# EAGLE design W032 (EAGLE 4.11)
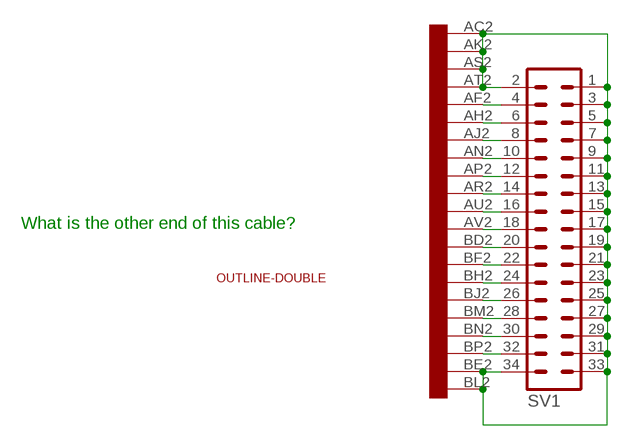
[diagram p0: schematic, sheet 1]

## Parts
SV1  MA17-2  [MA17-2]
U$1  OUTLINE-DOUBLE  [DOUBLE]
U$2  DOUBLE  [EDGE-CON4]

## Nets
GND: SV1.1 SV1.2 SV1.3 SV1.5 SV1.7 SV1.9 SV1.11 SV1.13 SV1.15 SV1.17 SV1.19 SV1.21 SV1.23 SV1.25 SV1.27 SV1.29 SV1.31 SV1.33 SV1.34 U$2.AC2 U$2.AK2 U$2.AS2 U$2.AT2 U$2.BE2 U$2.BL2
N$2: SV1.4 U$2.AF2
N$3: SV1.6 U$2.AH2
N$4: SV1.8 U$2.AJ2
N$5: SV1.10 U$2.AN2
N$6: SV1.12 U$2.AP2
N$7: SV1.14 U$2.AR2
N$8: SV1.16 U$2.AU2
N$9: SV1.18 U$2.AV2
N$10: SV1.20 U$2.BD2
N$11: SV1.22 U$2.BF2
N$12: SV1.24 U$2.BH2
N$13: SV1.26 U$2.BJ2
N$14: SV1.28 U$2.BM2
N$15: SV1.30 U$2.BN2
N$16: SV1.32 U$2.BP2
Unconnected: U$2.AA1 U$2.AA2 U$2.AB1 U$2.AB2 U$2.AC1 U$2.AD1 U$2.AD2 U$2.AE1 U$2.AE2 U$2.AF1 U$2.AH1 U$2.AJ1 U$2.AK1 U$2.AL1 U$2.AL2 U$2.AM1 U$2.AM2 U$2.AN1 U$2.AP1 U$2.AR1 U$2.AS1 U$2.AT1 U$2.AU1 U$2.AV1 U$2.BA1 U$2.BA2 U$2.BB1 U$2.BB2 U$2.BC1 U$2.BC2 U$2.BD1 U$2.BE1 U$2.BF1 U$2.BH1 U$2.BJ1 U$2.BK1 U$2.BK2 U$2.BL1 U$2.BM1 U$2.BN1 U$2.BP1 U$2.BR1 U$2.BR2 U$2.BS1 U$2.BS2 U$2.BT1 U$2.BT2 U$2.BU1 U$2.BU2 U$2.BV1 U$2.BV2

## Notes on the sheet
- What is the other end of this cable?

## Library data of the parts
SV1 = con-lstb:MA17-2: PIN HEADER
U$1 = dec-con:OUTLINE-*: Board outlines for DEC boards.
U$2 = dec-con:DOUBLE: Double-Height DEC board

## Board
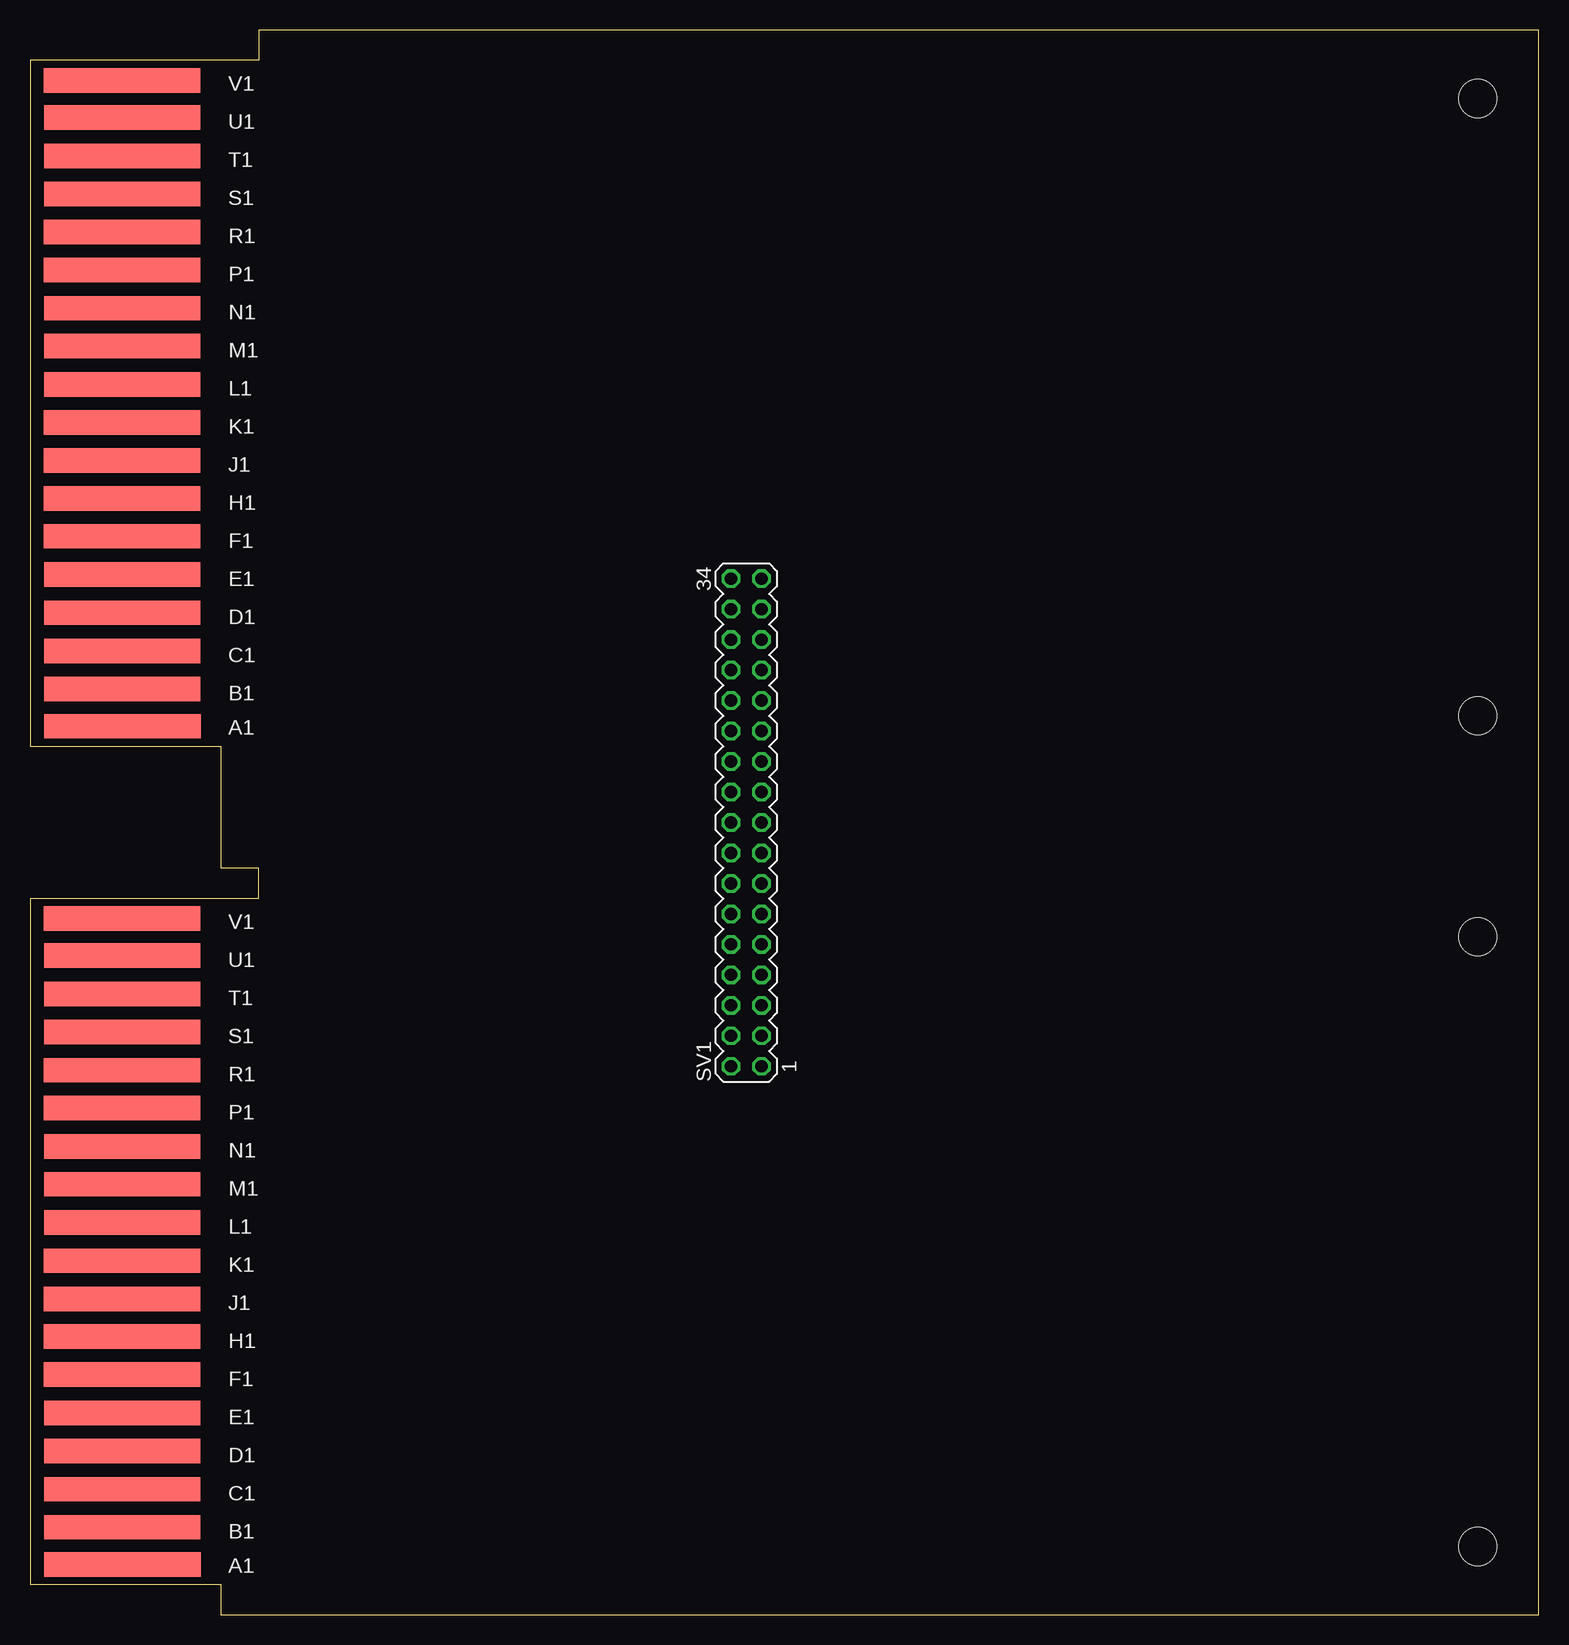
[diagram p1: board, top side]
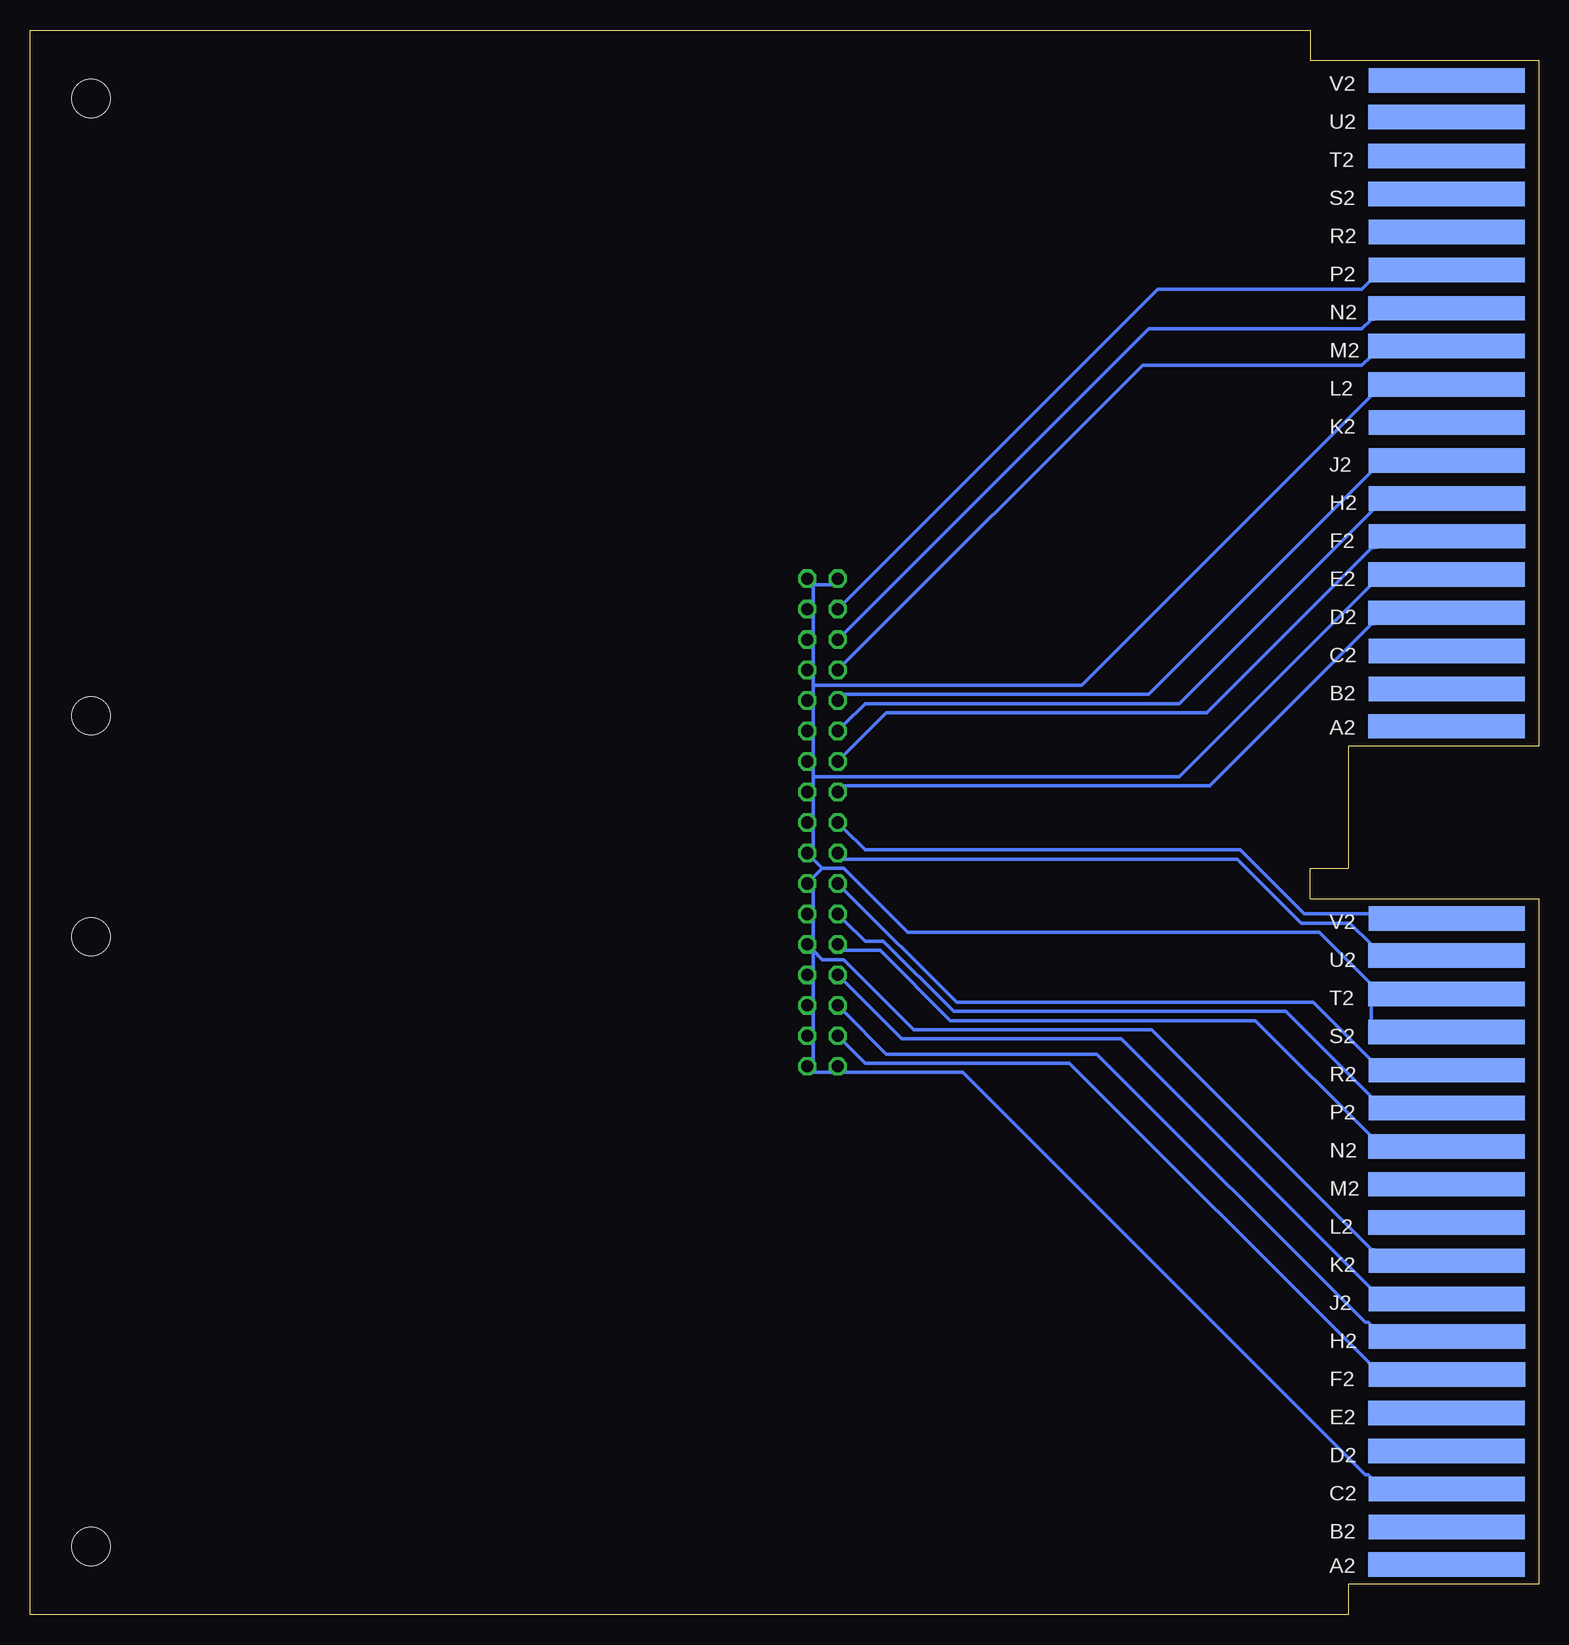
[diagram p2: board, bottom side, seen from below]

Size 125.73 x 132.08 mm. Coordinates in mm from the lower left corner, seen from the top.
Copper layers (1*16): Top 0.035mm / dielectric 1.5mm / Bottom 0.035mm
Design rules "10mils": minimum track width 12mil, minimum drill 28mil, track to track 10mil, track to pad 10mil, pad to pad 10mil, via to via 10mil, smd to smd 10mil, copper to edge 40mil, drill to drill 10mil, minimum pad ring 10mil, minimum via ring 20mil, stop-mask expansion 0mil, vias tented up to drill 0mil, thermal gap 10mil
vRestrict: area 31.8,108 to 41.9,125.7; area 49.5,108 to 59.7,125.7; area 67.3,108 to 77.5,125.7; area 85.1,108 to 95.3,125.7; area 102.9,108 to 113,125.7; area 31.8,80 to 41.9,97.8; area 49.5,80 to 59.7,97.8; area 67.3,80 to 77.5,97.8; area 85.1,80 to 95.3,97.8; area 31.8,34.3 to 41.9,52.1; area 49.5,34.3 to 59.7,52.1; area 67.3,34.3 to 77.5,52.1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

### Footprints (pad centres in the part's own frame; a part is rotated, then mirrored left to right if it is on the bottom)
MA17-2 = drill 1.016 octagon: 1 -20.32,-1.27; 2 -20.32,1.27; 3 -17.78,-1.27; 4 -17.78,1.27; 5 -15.24,-1.27; 6 -15.24,1.27; 7 -12.7,-1.27; 8 -12.7,1.27; 9 -10.16,-1.27; 10 -10.16,1.27; 11 -7.62,-1.27; 12 -7.62,1.27; 13 -5.08,-1.27; 14 -5.08,1.27; 15 -2.54,-1.27; 16 -2.54,1.27; 17 0,-1.27; 18 0,1.27; 19 2.54,-1.27; 20 2.54,1.27; 21 5.08,-1.27; 22 5.08,1.27; 23 7.62,-1.27; 24 7.62,1.27; 25 10.16,-1.27; 26 10.16,1.27; 27 12.7,-1.27; 28 12.7,1.27; 29 15.24,-1.27; 30 15.24,1.27; 31 17.78,-1.27; 32 17.78,1.27; 33 20.32,-1.27; 34 20.32,1.27
DOUBLE = hole 3.175: 120.65,56.515; 120.65,5.715; 120.65,74.93; 120.65,126.365
EDGE-CON4 = smd 13.017 x 2.032: AA1 7.709,4.207; AB1 7.684,7.312; AC1 7.684,10.474; AD1 7.684,13.665; AE1 7.693,16.84; AF1 7.668,20.041; AH1 7.668,23.19; AJ1 7.668,26.34; AK1 7.668,29.515; AL1 7.693,32.69; AM1 7.693,35.89; AN1 7.693,39.04; AP1 7.668,42.24; AR1 7.668,45.39; AS1 7.693,48.565; AT1 7.693,51.74; AU1 7.693,54.94; AV1 7.668,58.026; BA1 7.709,74.057; BB1 7.684,77.162; BC1 7.684,80.324; BD1 7.684,83.515; BE1 7.693,86.69; BF1 7.668,89.891; BH1 7.668,93.04; BJ1 7.668,96.19; BK1 7.668,99.365; BL1 7.693,102.54; BM1 7.693,105.74; BN1 7.693,108.89; BP1 7.668,112.09; BR1 7.668,115.24; BS1 7.693,118.415; BT1 7.693,121.59; BU1 7.693,124.79; BV1 7.668,127.876 | smd 13.017 x 2.032 bottom: AA2 7.69,4.207; AB2 7.668,7.328; AC2 7.668,10.49; AD2 7.693,13.665; AE2 7.693,16.84; AF2 7.642,20.041; AH2 7.642,23.19; AJ2 7.668,26.34; AK2 7.668,29.515; AL2 7.693,32.69; AM2 7.693,35.89; AN2 7.693,39.04; AP2 7.668,42.24; AR2 7.668,45.39; AS2 7.693,48.565; AT2 7.693,51.74; AU2 7.693,54.966; AV2 7.668,58.026; BA2 7.69,74.057; BB2 7.668,77.178; BC2 7.668,80.34; BD2 7.693,83.515; BE2 7.693,86.69; BF2 7.642,89.891; BH2 7.642,93.04; BJ2 7.668,96.19; BK2 7.668,99.365; BL2 7.693,102.54; BM2 7.693,105.74; BN2 7.693,108.89; BP2 7.668,112.09; BR2 7.668,115.24; BS2 7.693,118.415; BT2 7.693,121.59; BU2 7.693,124.816; BV2 7.668,127.876

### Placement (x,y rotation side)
SV1  59.69,66.04 90 top
U$1  0,0 0 top
U$2  0,0 0 top

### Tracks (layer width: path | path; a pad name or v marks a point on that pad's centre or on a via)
GND
  Bottom 0.305: 60.45,85.85 58.93,85.85 SV1.34 | 60.45,85.85 SV1.33 60.45,85.85 | SV1.9 60.45,56.39 60.45,57.91 SV1.11 60.45,58.93 60.45,60.45 SV1.13 60.45,61.47 59.69,62.23 | 60.45,69.85 60.45,69.09 SV1.19 60.45,68.07 60.45,66.55 SV1.17 60.45,65.53 60.45,64.01 SV1.15 60.45,62.99 59.69,62.23 | 60.45,69.85 60.45,70.61 SV1.21 60.45,71.63 60.45,73.15 SV1.23 60.45,74.17 60.45,75.69 SV1.25 60.45,76.71 60.45,77.47 | 60.45,77.47 60.45,78.23 SV1.27 60.45,79.25 60.45,80.77 SV1.29 60.45,81.79 60.45,83.31 SV1.31 60.45,84.33 60.45,85.85 | 60.45,69.85 29.97,69.85 13.97,85.85 | 60.45,77.47 38.1,77.47 19.56,96.01 13.97,101.6 | U$2.AS2 13.97,49.53 13.97,50.8 U$2.AT2 13.97,52.58 18.29,56.9 52.58,56.9 57.91,62.23 59.69,62.23 | U$2.AC2 13.97,11.43 14.22,11.68 14.48,11.68 48.01,45.21 57.91,45.21 SV1.2 58.93,45.21 60.45,45.21 SV1.1 60.45,46.23 60.45,47.75 SV1.3 60.45,48.77 60.45,50.29 SV1.5 60.45,51.31 60.45,52.83 SV1.7 60.45,53.85 60.45,55.37 | 13.97,85.85 U$2.BE2 13.97,85.85 | 13.97,101.6 U$2.BL2 13.97,101.6 | 60.45,55.37 59.69,54.61 57.91,54.61 52.07,48.77 32.26,48.77 13.97,30.48 U$2.AK2 | 60.45,55.37 SV1.9 | 60.45,55.37 SV1.9
N$2
  Bottom 0.305: SV1.4 57.91,47.75 56.13,45.97 39.12,45.97 14.48,21.34 13.97,20.83 U$2.AF2
N$3
  Bottom 0.305: SV1.6 57.91,50.29 54.36,46.74 36.83,46.74 14.48,24.38 14.22,24.38 13.97,24.13 U$2.AH2
N$4
  Bottom 0.305: SV1.8 57.91,52.83 53.09,48.01 34.8,48.01 14.48,27.69 13.97,27.18 U$2.AJ2
N$5
  Bottom 0.305: SV1.10 57.91,55.37 54.86,55.37 49.02,49.53 23.62,49.53 13.97,39.88 U$2.AN2
N$6
  Bottom 0.305: SV1.12 57.91,57.91 56.13,56.13 54.61,56.13 48.77,50.29 21.08,50.29 13.97,43.18 U$2.AP2
N$7
  Bottom 0.305: SV1.14 57.91,60.45 48.51,51.05 18.8,51.05 14.48,46.74 13.97,46.23 U$2.AR2
N$8
  Bottom 0.305: SV1.16 57.91,62.99 25.15,62.99 19.81,57.66 15.75,57.66 13.97,55.88 U$2.AU2
N$9
  Bottom 0.305: SV1.18 57.91,65.53 56.13,63.75 24.89,63.75 19.56,58.42 13.97,58.42 U$2.AV2
N$10
  Bottom 0.305: SV1.20 57.91,69.09 27.43,69.09 13.97,82.55 U$2.BD2
N$11
  Bottom 0.305: SV1.22 57.91,71.63 54.36,75.18 27.69,75.18 13.97,88.9 | 13.97,88.9 U$2.BF2 13.97,88.9
N$12
  Bottom 0.305: SV1.24 57.91,74.17 56.13,75.95 29.97,75.95 13.72,92.2 U$2.BH2 13.97,92.2
N$13
  Bottom 0.305: SV1.26 57.91,76.71 32.51,76.71 13.97,95.25 U$2.BJ2
N$14
  Bottom 0.305: SV1.28 57.91,79.25 33.02,104.14 14.73,104.14 13.97,104.9 U$2.BM2
N$15
  Bottom 0.305: SV1.30 57.91,81.79 32.51,107.19 14.73,107.19 13.97,107.95 U$2.BN2
N$16
  Bottom 0.305: SV1.32 57.91,84.33 31.75,110.49 14.73,110.49 13.97,111.25 U$2.BP2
